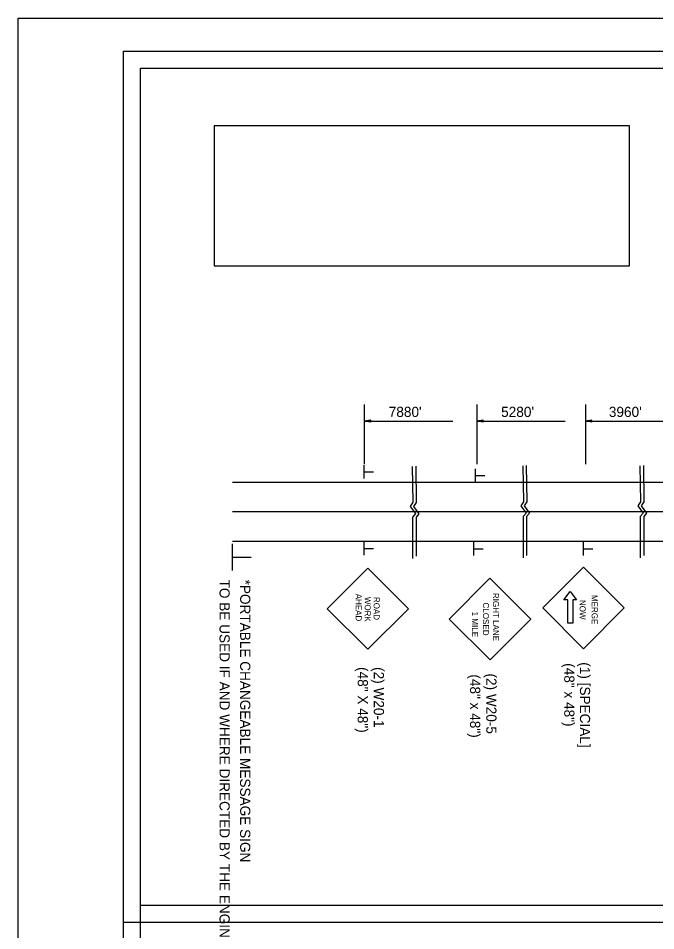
# Model space of a CAD drawing. Extents: x 1373222 to 1374279, y 380783 to 380996.
# Drawn here: x 1373583.7 to 1373658.8, y 380888.9 to 380996.5 of the extents above; entities that cross this region are included whole.
import ezdxf

# ---------------------------------------------------------------- set-up
doc = ezdxf.new("R2010")
doc.units = 0
for name, color, linetype in [('Default', 7, 'Continuous'), ('R_Border', 7, 'Continuous'), ('R_Border Plan-Plan', 7, 'Continuous'), ('R_Draft', 7, 'Continuous'), ('R_No Plot', 7, 'Continuous')]:
    doc.layers.add(name, color=color, linetype=linetype)

msp = doc.modelspace()

# ---------------------------------------------------------------- linework, layer by layer
at = {"layer": 'Default'}
for p, q in [((1373624.49, 380950.92), (1373624.49, 380943.88)), ((1373637.74, 380950.92), (1373637.74, 380943.88)), ((1373650.57, 380950.92), (1373650.57, 380943.88)), ((1373625.24, 380949.08), (1373624.49, 380948.97)), ((1373624.49, 380948.97), (1373634.93, 380948.97)), ((1373625.24, 380948.85), (1373624.49, 380948.97)), ((1373625.24, 380949.06), (1373624.61, 380948.97)), ((1373625.24, 380948.87), (1373624.61, 380948.97)), ((1373625.24, 380949.04), (1373624.74, 380948.97)), ((1373625.24, 380948.89), (1373624.74, 380948.97)), ((1373625.24, 380949.02), (1373624.87, 380948.97)), ((1373625.24, 380948.91), (1373624.87, 380948.97)), ((1373625.24, 380949), (1373624.99, 380948.97)), ((1373625.24, 380948.93), (1373624.99, 380948.97)), ((1373625.24, 380948.98), (1373625.12, 380948.97)), ((1373625.24, 380948.95), (1373625.12, 380948.97)), ((1373625.24, 380948.85), (1373625.24, 380949.08)), ((1373638.49, 380949.08), (1373637.74, 380948.97)), ((1373637.74, 380948.97), (1373648.17, 380948.97)), ((1373638.49, 380948.85), (1373637.74, 380948.97)), ((1373638.49, 380949.06), (1373637.86, 380948.97)), ((1373638.49, 380948.87), (1373637.86, 380948.97)), ((1373638.49, 380949.04), (1373637.99, 380948.97)), ((1373638.49, 380948.89), (1373637.99, 380948.97)), ((1373638.49, 380949.02), (1373638.12, 380948.97)), ((1373638.49, 380948.91), (1373638.12, 380948.97)), ((1373638.49, 380949), (1373638.24, 380948.97)), ((1373638.49, 380948.93), (1373638.24, 380948.97)), ((1373638.49, 380948.98), (1373638.37, 380948.97)), ((1373638.49, 380948.95), (1373638.37, 380948.97)), ((1373638.49, 380948.85), (1373638.49, 380949.08)), ((1373651.32, 380949.08), (1373650.57, 380948.97)), ((1373650.57, 380948.97), (1373661.01, 380948.97)), ((1373651.32, 380948.85), (1373650.57, 380948.97)), ((1373651.32, 380949.06), (1373650.69, 380948.97)), ((1373651.32, 380948.87), (1373650.69, 380948.97)), ((1373651.32, 380949.04), (1373650.82, 380948.97)), ((1373651.32, 380948.89), (1373650.82, 380948.97)), ((1373651.32, 380949.02), (1373650.95, 380948.97)), ((1373651.32, 380948.91), (1373650.95, 380948.97)), ((1373651.32, 380949), (1373651.07, 380948.97)), ((1373651.32, 380948.93), (1373651.07, 380948.97)), ((1373651.32, 380948.98), (1373651.2, 380948.97)), ((1373651.32, 380948.95), (1373651.2, 380948.97)), ((1373651.32, 380948.85), (1373651.32, 380949.08)), ((1373624.49, 380942.21), (1373624.49, 380943.78)), ((1373624.51, 380942.99), (1373625.58, 380942.99)), ((1373637.61, 380941.79), (1373637.61, 380943.36)), ((1373637.64, 380942.57), (1373638.7, 380942.57)), ((1373608.96, 380941.78), (1373892.42, 380941.78)), ((1373608.96, 380938.31), (1373892.42, 380938.31)), ((1373608.96, 380934.83), (1373892.42, 380934.83)), ((1373608.96, 380931.35), (1373608.96, 380934.48)), ((1373624.47, 380933.17), (1373624.47, 380934.74)), ((1373637.42, 380933.14), (1373637.42, 380934.71)), ((1373650.34, 380933.13), (1373650.34, 380934.7)), ((1373624.49, 380933.95), (1373625.56, 380933.95)), ((1373637.44, 380933.92), (1373638.51, 380933.92)), ((1373650.36, 380933.91), (1373651.43, 380933.91)), ((1373609.01, 380932.91), (1373611.15, 380932.91)), ((1373620.13, 380926.85), (1373624.91, 380931.63)), ((1373629.69, 380926.85), (1373624.91, 380931.63)), ((1373645.52, 380926.93), (1373650.33, 380931.75)), ((1373655.14, 380926.95), (1373650.33, 380931.75)), ((1373634.49, 380925.61), (1373639.29, 380930.43)), ((1373644.11, 380925.62), (1373639.29, 380930.43)), ((1373648.02, 380927.9), (1373648.77, 380928.88)), ((1373648.77, 380928.88), (1373649.52, 380927.9)), ((1373648.49, 380927.9), (1373648.02, 380927.9)), ((1373648.49, 380925.15), (1373648.49, 380927.9)), ((1373649.06, 380927.9), (1373649.06, 380925.15)), ((1373649.52, 380927.9), (1373649.06, 380927.9)), ((1373624.91, 380922.06), (1373620.13, 380926.85)), ((1373624.91, 380922.06), (1373629.69, 380926.85)), ((1373650.34, 380922.13), (1373645.52, 380926.93)), ((1373650.34, 380922.13), (1373655.14, 380926.95)), ((1373639.31, 380920.8), (1373634.49, 380925.61)), ((1373639.31, 380920.8), (1373644.11, 380925.62)), ((1373649.06, 380925.15), (1373648.49, 380925.15))]:
    msp.add_line(p, q, dxfattribs=at)
for points in [[(1373630.15, 380943.61), (1373630.21, 380939.41), (1373629.89, 380938.92), (1373630.52, 380938.06), (1373630.19, 380937.66), (1373630.19, 380932.77)], [(1373630.55, 380943.65), (1373630.61, 380939.39), (1373630.29, 380938.91), (1373630.92, 380938.04), (1373630.59, 380937.64), (1373630.59, 380933.05)], [(1373643.19, 380943.68), (1373643.25, 380939.47), (1373642.93, 380938.99), (1373643.56, 380938.13), (1373643.23, 380937.73), (1373643.23, 380932.83)], [(1373643.59, 380943.72), (1373643.65, 380939.46), (1373643.33, 380938.97), (1373643.96, 380938.11), (1373643.63, 380937.71), (1373643.62, 380933.12)], [(1373656.99, 380943.68), (1373657.05, 380939.47), (1373656.73, 380938.99), (1373657.36, 380938.13), (1373657.03, 380937.73), (1373657.03, 380932.83)], [(1373657.39, 380943.72), (1373657.45, 380939.46), (1373657.13, 380938.97), (1373657.76, 380938.11), (1373657.43, 380937.71), (1373657.43, 380933.12)]]:
    msp.add_lwpolyline(points, dxfattribs=at)
at = {"layer": 'R_Border'}
for p, q in [((1373596.1, 380992.59), (1373912.28, 380992.59)), ((1373596.1, 380787.13), (1373596.1, 380992.59))]:
    msp.add_line(p, q, dxfattribs=at)
at = {"layer": 'R_Border Plan-Plan'}
msp.add_line((1373596.1, 380889.86), (1373912.28, 380889.86), dxfattribs=at)
at = {"layer": 'R_Draft'}
msp.add_lwpolyline([(1373606.78, 380967.28), (1373655.75, 380967.28), (1373655.75, 380983.81), (1373606.78, 380983.81)], close=True, dxfattribs=at)
at = {"layer": 'R_No Plot'}
for points in [[(1373583.69, 380996.49), (1373917.03, 380996.49), (1373917.03, 380783.15), (1373583.69, 380783.15)], [(1373910.28, 380891.86), (1373598.1, 380891.86), (1373598.1, 380990.59), (1373847.64, 380990.59), (1373847.64, 380980.71), (1373865.18, 380980.71), (1373889.28, 380980.71), (1373889.28, 380958.38), (1373910.28, 380958.38)], [(1373598.1, 380990.59), (1373847.64, 380990.59), (1373847.64, 380980.71), (1373865.18, 380980.71), (1373889.28, 380980.71), (1373889.28, 380958.38), (1373910.28, 380958.38), (1373910.28, 380789.13), (1373598.1, 380789.13)]]:
    msp.add_lwpolyline(points, close=True, dxfattribs=at)

# ---------------------------------------------------------------- texts
at = {"layer": 'Default'}
for s, p in [("7880'", (1373627.37, 380949.46)), ("5280'", (1373640.62, 380949.46)), ("3960'", (1373653.32, 380949.46))]:
    msp.add_text(s, height=1.2, dxfattribs=at).set_placement(p)
for s, height, rotation, p in [('TO BE USED IF AND WHERE DIRECTED BY THE ENGINEER', 1.2, 270, (1373607.42, 380930.28)), ('*PORTABLE CHANGEABLE MESSAGE SIGN', 1.2, 270, (1373609.85, 380930.28)), (' AHEAD', 0.704, 270.0006, (1373623.48, 380928.87)), ('WORK', 0.704, 270, (1373624.54, 380928.24)), ('ROAD', 0.704, 270.0004, (1373625.59, 380928.23)), ('RIGHT LANE', 0.709, 270.1004, (1373639.65, 380928.71)), ('NOW', 0.709, 270.1003, (1373649.87, 380927.88)), ('MERGE', 0.709, 270.1004, (1373651.29, 380928.47)), ('CLOSED', 0.709, 270.1003, (1373638.47, 380927.57)), ('1 MILE', 0.713, 270.0006, (1373637.19, 380926.51)), ('(48" x 48")', 1.2, 270, (1373648.06, 380920.42)), ('(1) [SPECIAL]', 1.2, 270, (1373649.91, 380920.53)), ('(48" X 48")', 1.2, 270, (1373623.71, 380919.96)), ('(2) W20-1', 1.2, 270, (1373625.61, 380919.96)), ('(48" x 48")', 1.2, 270, (1373636.96, 380919.1)), ('(2) W20-5', 1.2, 270, (1373638.87, 380919.21))]:
    msp.add_text(s, height=height, rotation=rotation, dxfattribs=at).set_placement(p)

doc.saveas('drawing.dxf')
